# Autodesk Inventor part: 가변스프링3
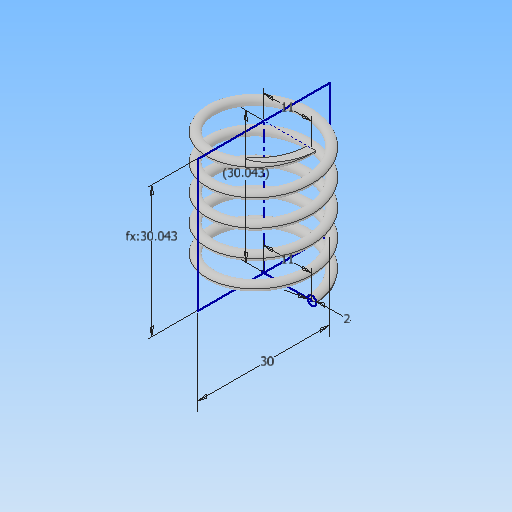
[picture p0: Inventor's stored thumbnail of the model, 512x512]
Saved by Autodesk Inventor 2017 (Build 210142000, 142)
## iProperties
Part Number: 가변스프링3
Material: 일반
Document SubType Name: Modeling
Designer: MRC
Density: 1 g/cm^3
Appearance: 기본값
Mass: 1.07047 g
Surface Area: 21.6867 cm^2
Volume: 1.07047 cm^3
Author: MRC
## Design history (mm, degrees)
sketch "스케치1"
  geometry: L1 (0, 0)-(0, 30.043); L2 (0, 0)-(11, 0); L3 (0, 30.043)-(11, 30.043); C1 r 1 at (11, 0)
  constraints: 6 end point, 1 centre point, 1 coincident, 1 horizontal, 1 parallel, 1 vertical
  dimensions: "d1" = 11 distance of L1.start L2.end; "d2" = 11 distance of L1.end L3.end; "d3" = 2 diameter of C1; "d4" = 30.04259 distance of L1.start L1.end (derived)
feature "코일1" sketch "스케치1" pitch "d5" = 10; turns "d7" = 5; dims "d6" = 30.04259 (= d4), "d8" = 0, angle "d9" = 90 deg, angle "d10" = 90 deg, "d11" = 0, "d12" = 0
sketch "스케치2"
  geometry: L1 (30.043, -15)-(0, -15); L2 (0, -15)-(0, 15); L3 (0, 15)-(30.043, 15); L4 (30.043, 15)-(30.043, -15); 2 further points
  constraints: 8 end point, 2 parallel, 1 coincident, 1 horizontal, 1 midpoint, 1 perpendicular
  dimensions: "d13" = 30.04259 distance of L2.end L3.end (= d4); "d14" = 30 distance of L1.end L2.end
extrude "돌출1" sketch "스케치2" stored distance "d15" = 0; taper "d16" = 0 deg
node "솔리드1"
